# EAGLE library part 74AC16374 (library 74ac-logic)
16-bit edge-triggered D-type FLIP FLOP, 3-state
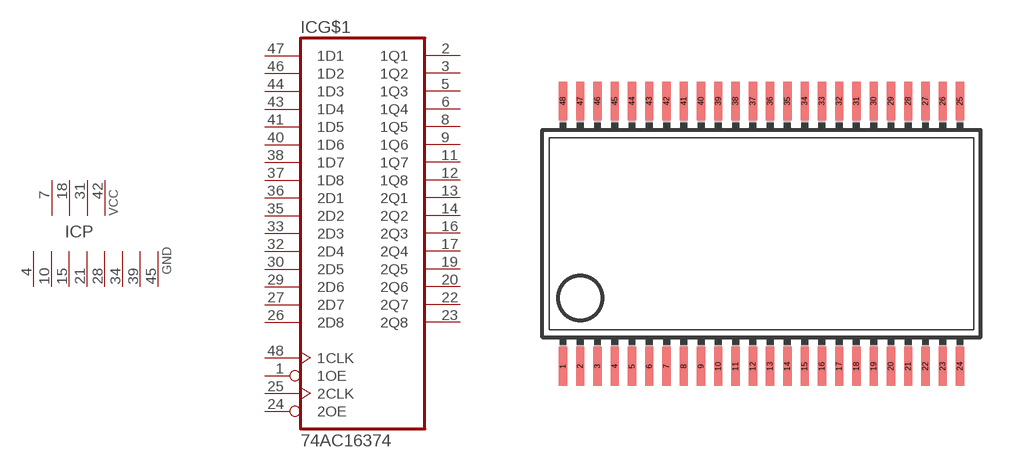
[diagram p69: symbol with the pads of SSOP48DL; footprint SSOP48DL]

Designator prefix IC; gates G$1=7416374 P=4PWR8GND

## 74AC16374  [SSOP48DL]
1  G$1:1OE  in
2  G$1:1Q1  hiz
3  G$1:1Q2  hiz
4  P:GND  pwr
5  G$1:1Q3  hiz
6  G$1:1Q4  hiz
7  P:VCC  pwr
8  G$1:1Q5  hiz
9  G$1:1Q6  hiz
10  P:GND  pwr
11  G$1:1Q7  hiz
12  G$1:1Q8  hiz
13  G$1:2Q1  hiz
14  G$1:2Q2  hiz
15  P:GND  pwr
16  G$1:2Q3  hiz
17  G$1:2Q4  hiz
18  P:VCC  pwr
19  G$1:2Q5  hiz
20  G$1:2Q6  hiz
21  P:GND  pwr
22  G$1:2Q7  hiz
23  G$1:2Q8  hiz
24  G$1:2OE  in
25  G$1:2CLK  in
26  G$1:2D8  in
27  G$1:2D7  in
28  P:GND  pwr
29  G$1:2D6  in
30  G$1:2D5  in
31  P:VCC  pwr
32  G$1:2D4  in
33  G$1:2D3  in
34  P:GND  pwr
35  G$1:2D2  in
36  G$1:2D1  in
37  G$1:1D8  in
38  G$1:1D7  in
39  P:GND  pwr
40  G$1:1D6  in
41  G$1:1D5  in
42  P:VCC  pwr
43  G$1:1D4  in
44  G$1:1D3  in
45  P:GND  pwr
46  G$1:1D2  in
47  G$1:1D1  in
48  G$1:1CLK  in

## Footprint SSOP48DL (pad centres in mm)
Shrink Small Outline Package
smd 0.305 x 1.422: 1 -6.985,-4.877; 2 -6.35,-4.877; 3 -5.715,-4.877; 4 -5.08,-4.877; 5 -4.445,-4.877; 6 -3.81,-4.877; 7 -3.175,-4.877; 8 -2.54,-4.877; 9 -1.905,-4.877; 10 -1.27,-4.877; 11 -0.635,-4.877; 12 0,-4.877; 13 0.635,-4.877; 14 1.27,-4.877; 15 1.905,-4.877; 16 2.54,-4.877; 17 3.175,-4.877; 18 3.81,-4.877; 19 4.445,-4.877; 20 5.08,-4.877; 21 5.715,-4.877; 22 6.35,-4.877; 23 6.985,-4.877; 24 7.62,-4.877; 25 7.62,4.877; 26 6.985,4.877; 27 6.35,4.877; 28 5.715,4.877; 29 5.08,4.877; 30 4.445,4.877; 31 3.81,4.877; 32 3.175,4.877; 33 2.54,4.877; 34 1.905,4.877; 35 1.27,4.877; 36 0.635,4.877; 37 0,4.877; 38 -0.635,4.877; 39 -1.27,4.877; 40 -1.905,4.877; 41 -2.54,4.877; 42 -3.175,4.877; 43 -3.81,4.877; 44 -4.445,4.877; 45 -5.08,4.877; 46 -5.715,4.877; 47 -6.35,4.877; 48 -6.985,4.877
